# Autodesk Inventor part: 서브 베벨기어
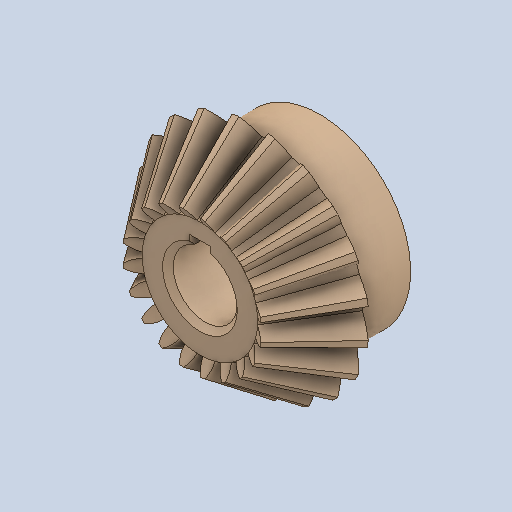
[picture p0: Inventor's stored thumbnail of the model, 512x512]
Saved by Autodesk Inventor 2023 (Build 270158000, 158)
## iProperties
Created: 2025-04
Part Number: 서브 베벨기어
Material: 강철, 탄소
Document SubType Name: Modeling
Designer: User
Density: 7.87 g/cm^3
Appearance: 기본값
Author: jhkim
Revision Number: 1
Sending System: Autodesk Inventor 2026
Preprocessor: ST-DEVELOPER v20.1
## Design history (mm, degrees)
node "복구된 형상1"
  node "스케치11"
feature "Solid1"
node "스케치10"
node "솔리드1"
